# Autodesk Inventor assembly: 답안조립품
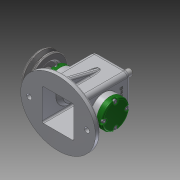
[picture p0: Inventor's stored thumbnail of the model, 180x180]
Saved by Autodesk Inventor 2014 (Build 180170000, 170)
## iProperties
Created: 2017-07
Part Number: 답안조립품
Document SubType Name: Assembly
Designer: user
Author: user
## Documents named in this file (16)
- C:\Users\user\Desktop\470708V1005\답안조립품.iam
- C:\Users\user\Desktop\470708V1005\1-본체.ipt
- C:\Users\user\Desktop\470708V1005\V벨트풀리.ipt
- C:\Users\user\Desktop\470708V1005\고정핀 1.2 x  8.ipt
- C:\Users\user\Desktop\470708V1005\뒤커버.ipt
- C:\Users\user\Desktop\470708V1005\링크.ipt
- C:\Users\user\Desktop\470708V1005\멈춤나사 M3x8.ipt
- C:\Users\user\Desktop\470708V1005\베어링 12 x 32 x 10.ipt
- C:\Users\user\Desktop\470708V1005\볼트 M4 x 12.ipt
- C:\Users\user\Desktop\470708V1005\부시.ipt
- C:\Users\user\Desktop\470708V1005\슬라이드.ipt
- C:\Users\user\Desktop\470708V1005\앞커버.ipt
- C:\Users\user\Desktop\470708V1005\오일실 12 25 7.ipt
- C:\Users\user\Desktop\470708V1005\키 4 x 4 x 10.ipt
- C:\Users\user\Desktop\470708V1005\편심축.ipt
- C:\Users\user\Desktop\470708V1005\핀 5 x 18.ipt
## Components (4 placed, 4 different names)
1. 1-본체:1 — Mate:8, Mate:9, Mate:10, Mate:11, Mate:12, Mate:13, Mate:14, Mate:16, Mate:22, Flush:2, Mate:29
2. V벨트풀리:1 — Mate:19, Mate:20
3. 핀 5 x 18:1 — Mate:24, Mate:25, Mate:26, Mate:28
4. 고정핀 1.2 x  8:1 — Mate:28
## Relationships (17: Mate 16, Flush 1)
- Mate:8: 1-본체:1
- Mate:9: 1-본체:1
- Mate:10: 1-본체:1
- Mate:11: 1-본체:1
- Mate:12: 1-본체:1
- Mate:13: 1-본체:1
- Mate:14: 1-본체:1
- Mate:16: 1-본체:1
- Mate:19: V벨트풀리:1
- Mate:20: V벨트풀리:1
- Mate:22: 1-본체:1
- Flush:2: 1-본체:1
- Mate:24: 핀 5 x 18:1
- Mate:25: 핀 5 x 18:1
- Mate:26: 핀 5 x 18:1
- Mate:28: 핀 5 x 18:1 ↔ 고정핀 1.2 x  8:1
- Mate:29: 1-본체:1
